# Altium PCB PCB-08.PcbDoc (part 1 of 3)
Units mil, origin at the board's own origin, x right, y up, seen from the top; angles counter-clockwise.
Board outline 2372.23 x 1978.53 mil, 4 copper layers (Top Layer, Plane-1, Plane-2, Bottom Layer), stack 84.834 mil thick; 206 components, 83 nets, 492 pads, 242 vias.
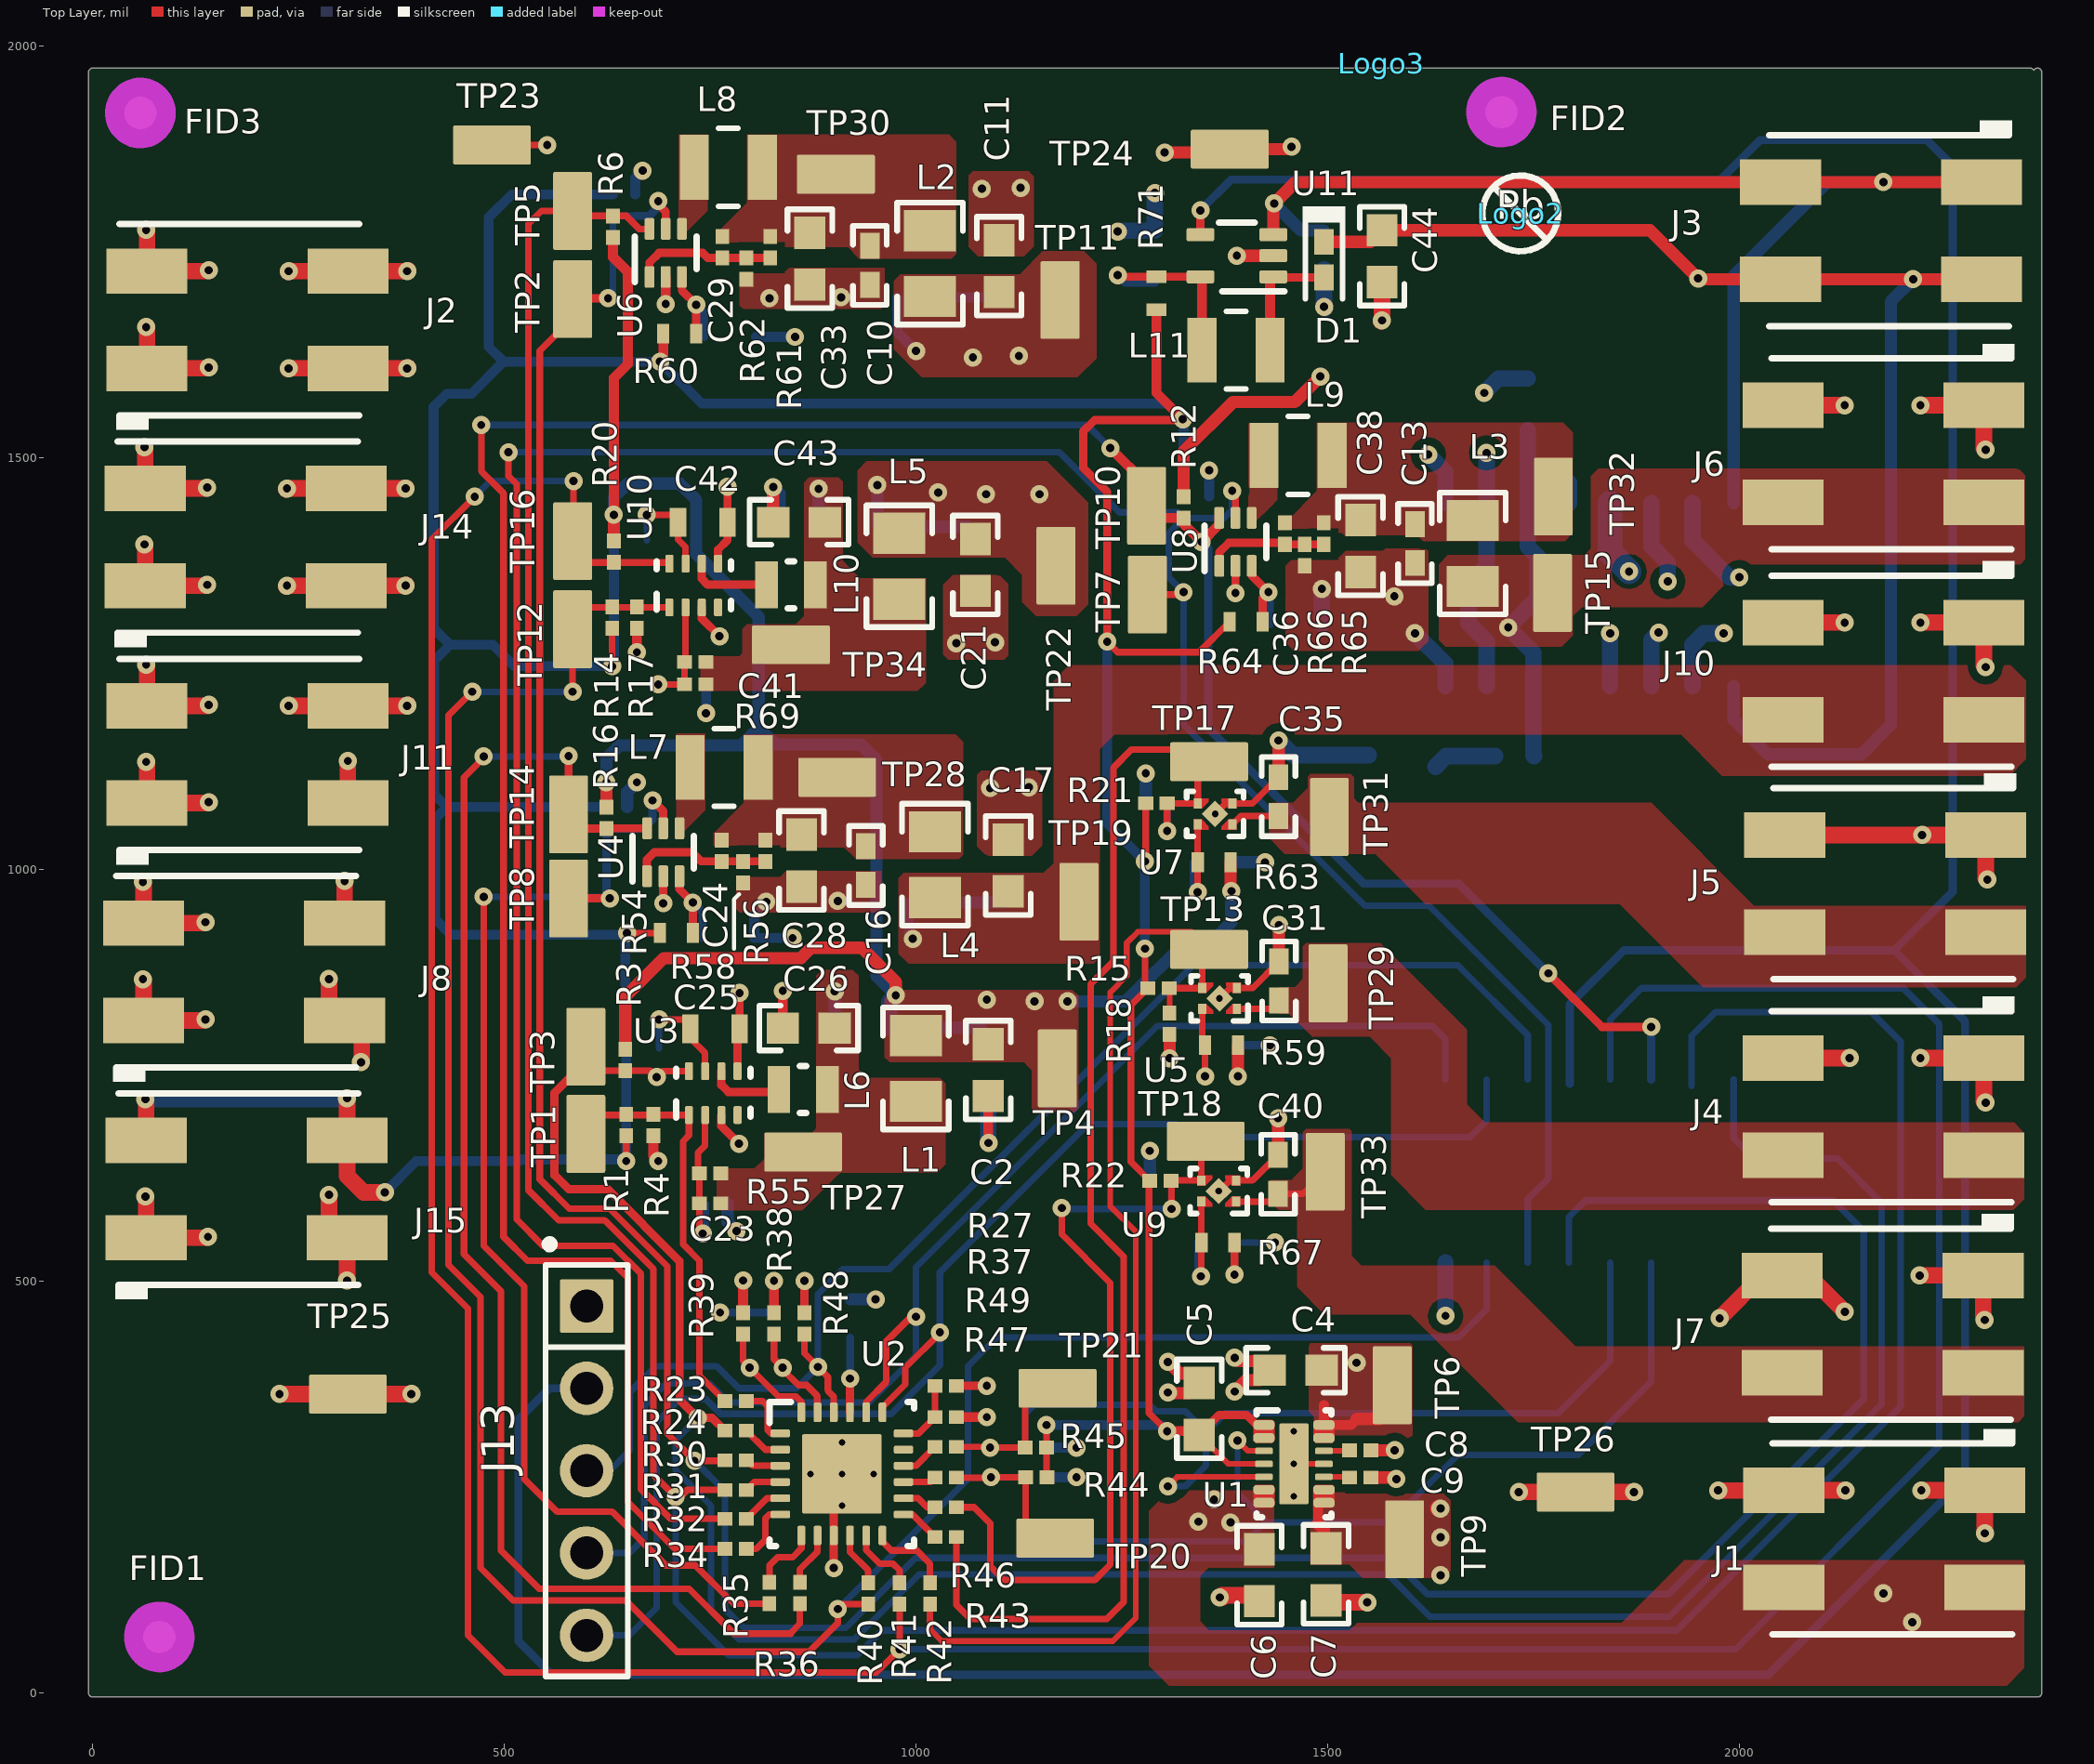
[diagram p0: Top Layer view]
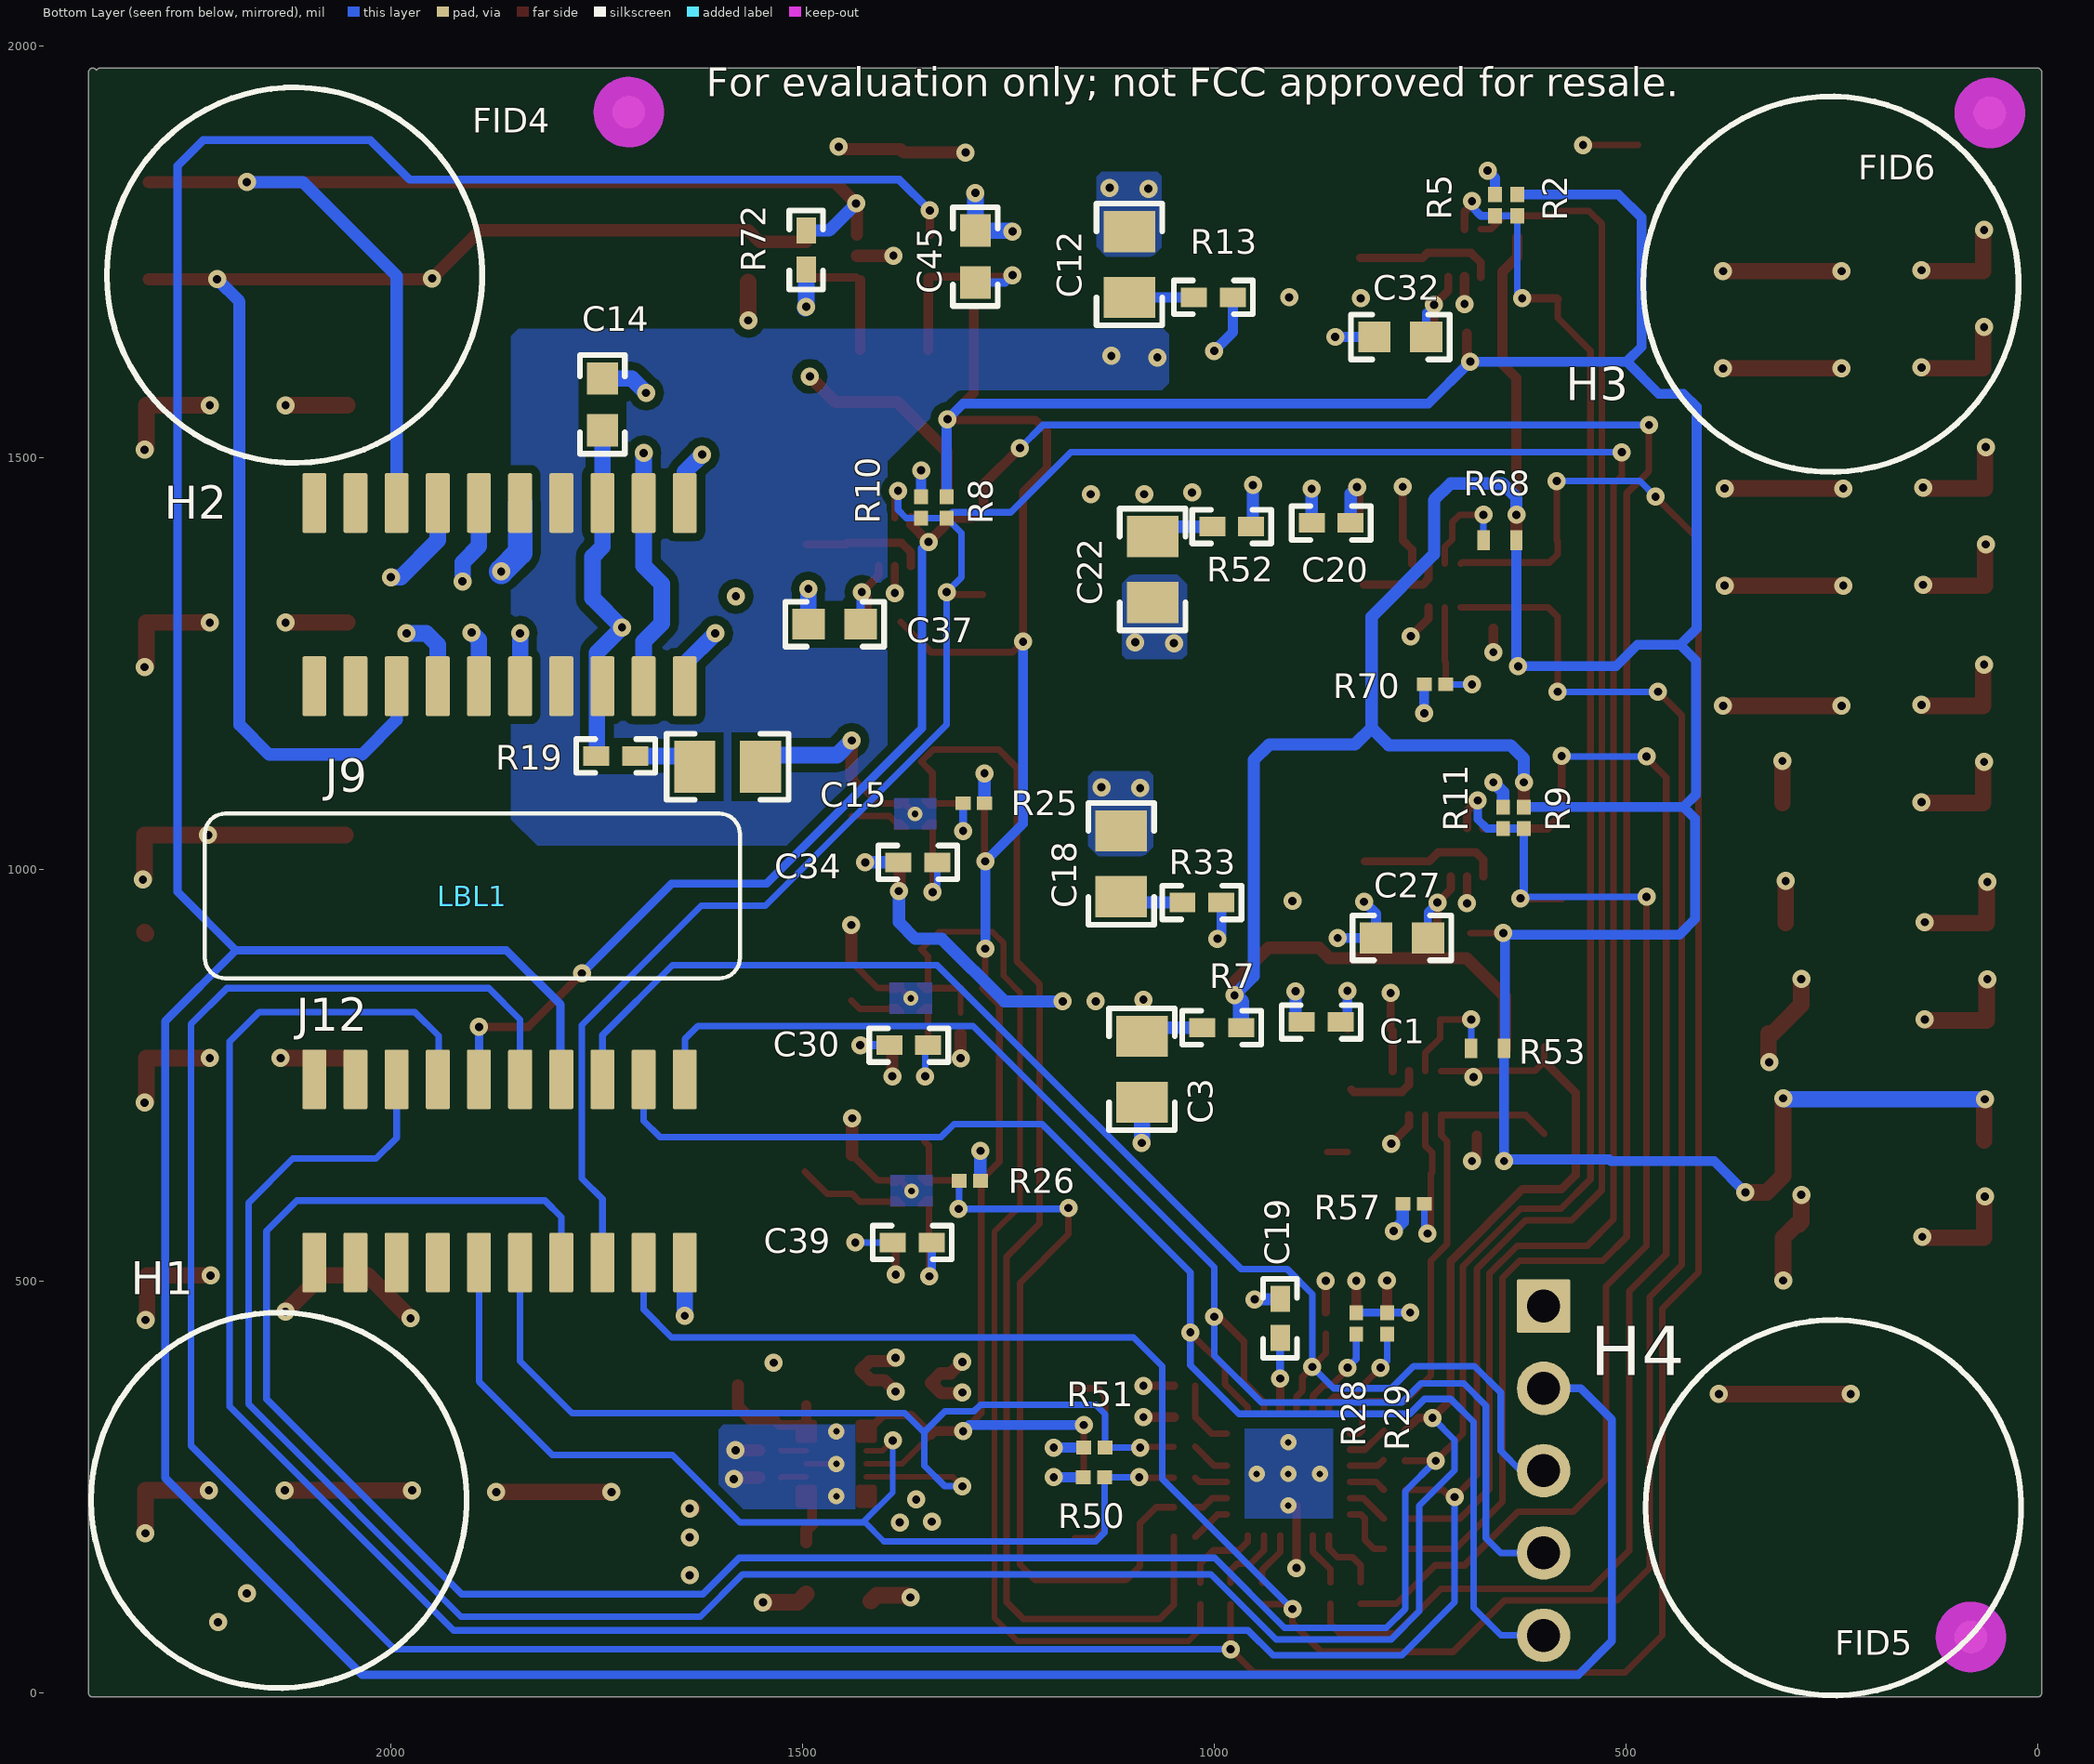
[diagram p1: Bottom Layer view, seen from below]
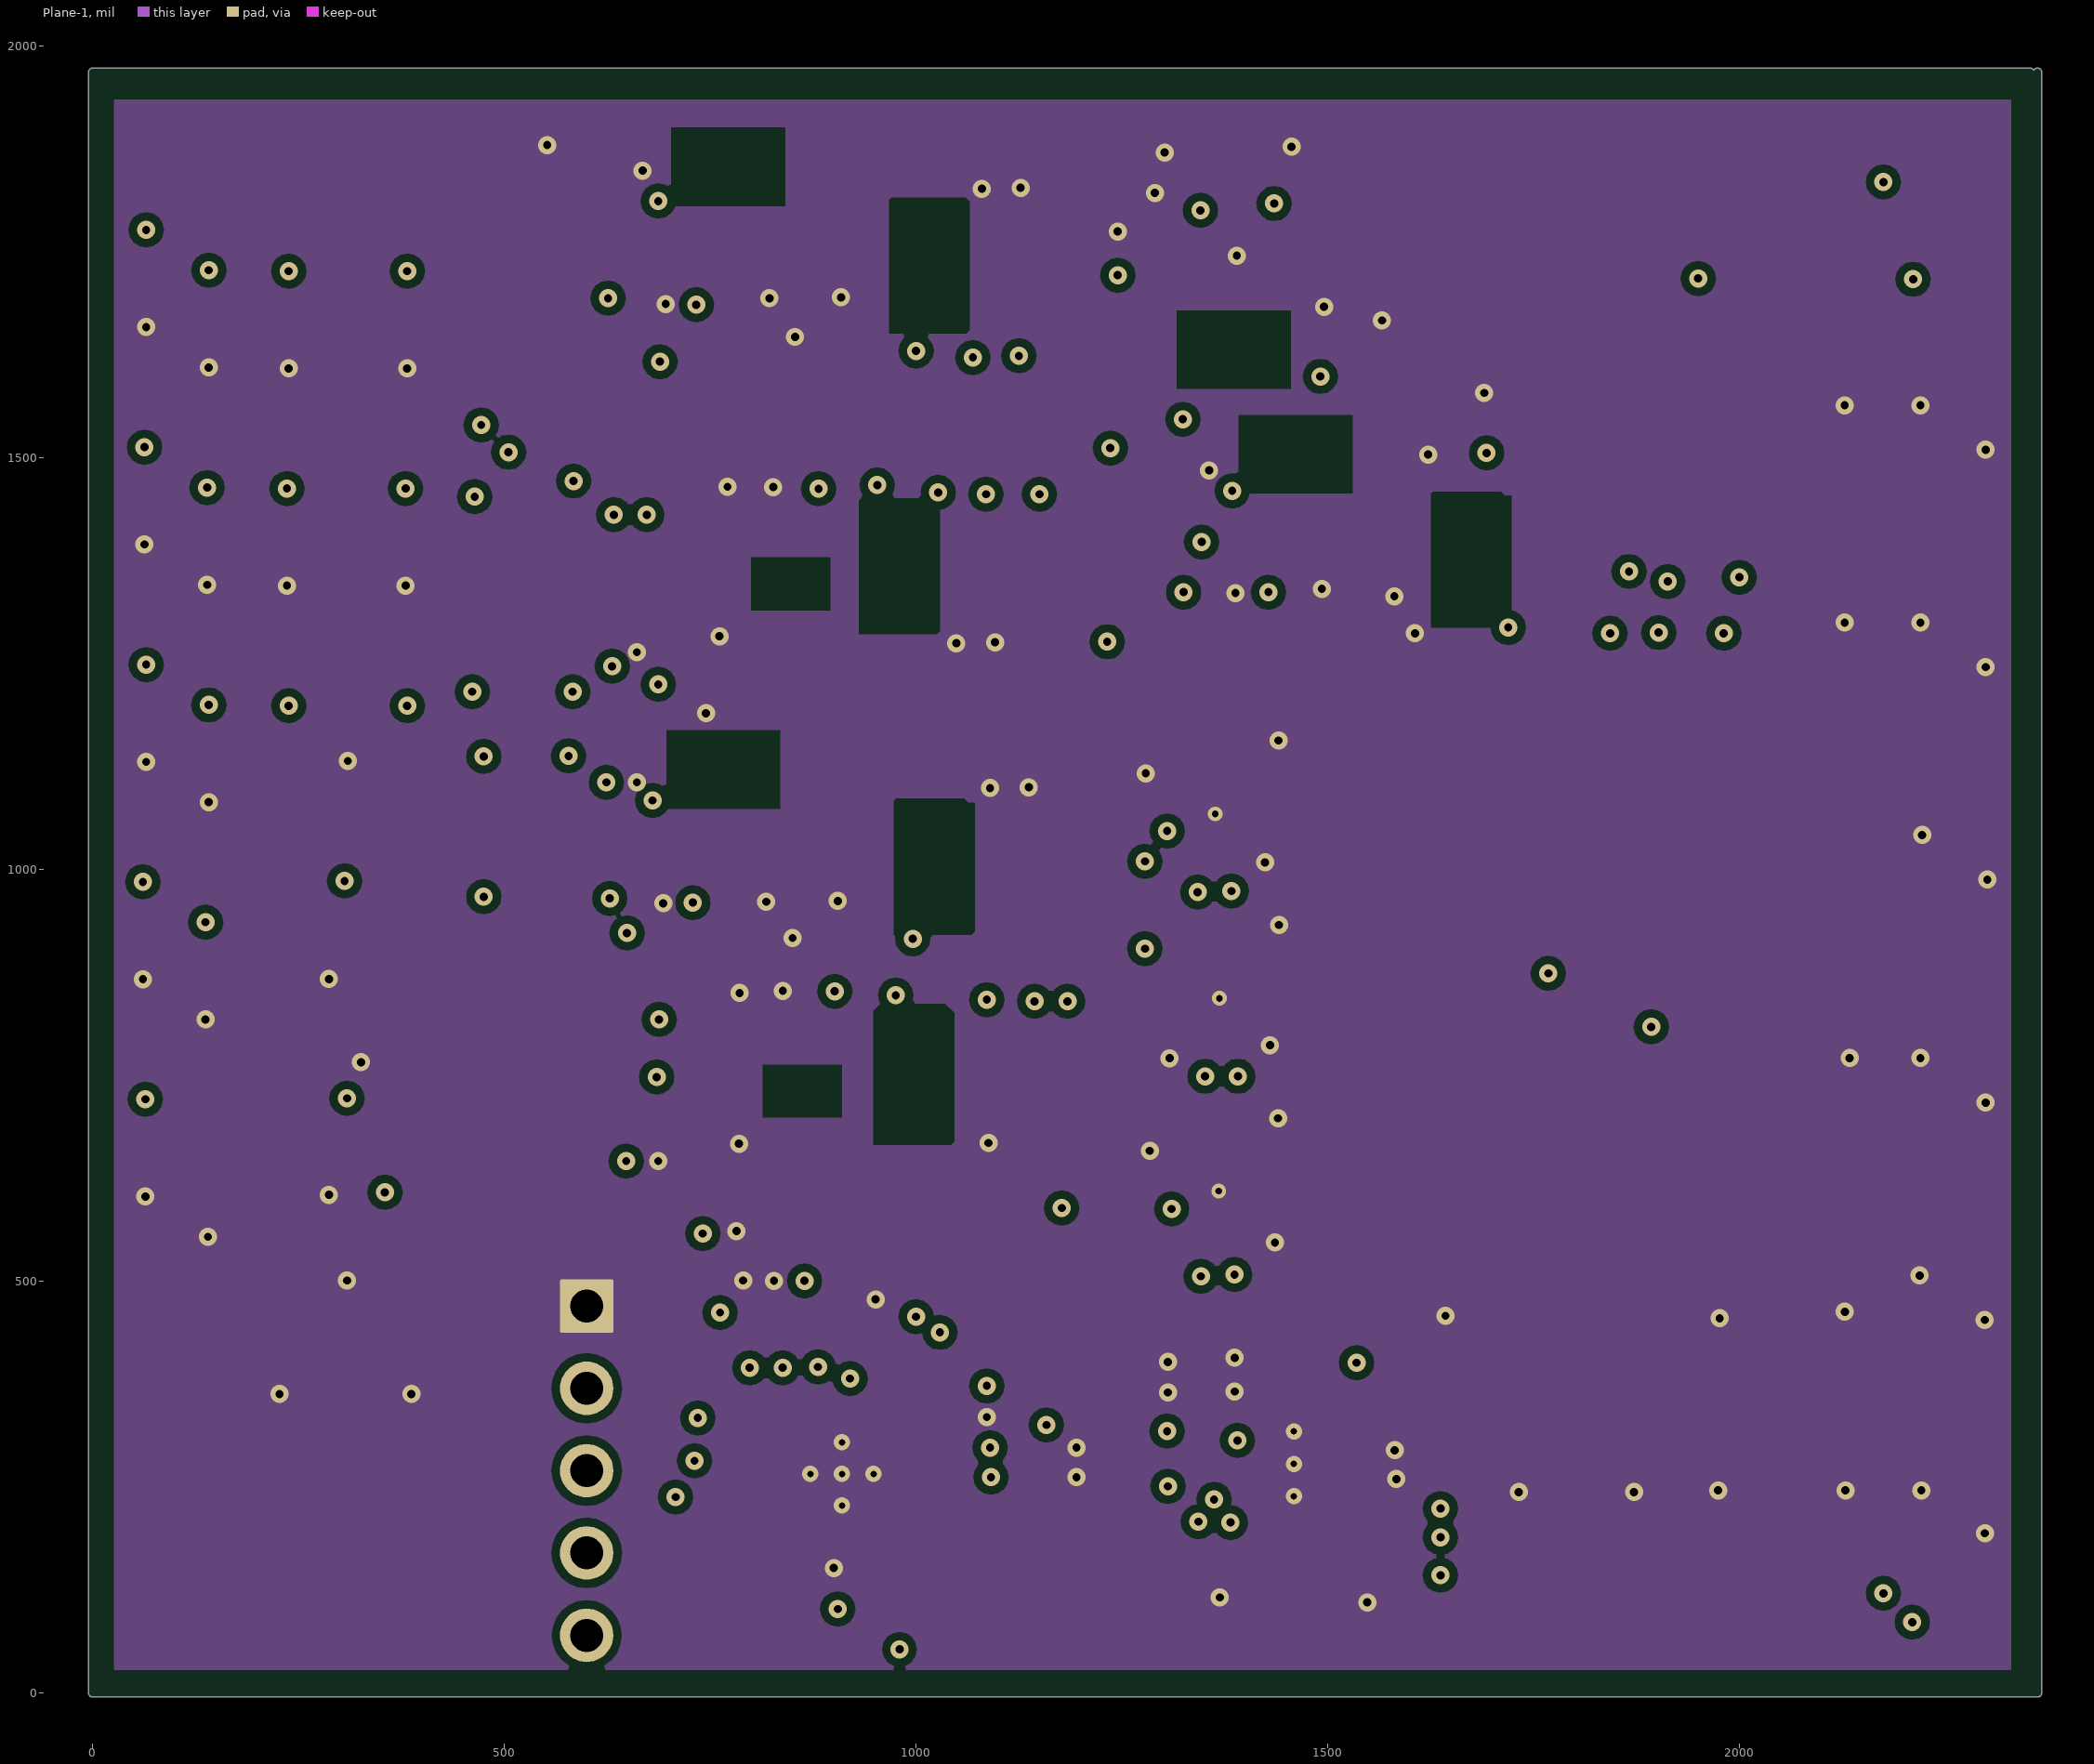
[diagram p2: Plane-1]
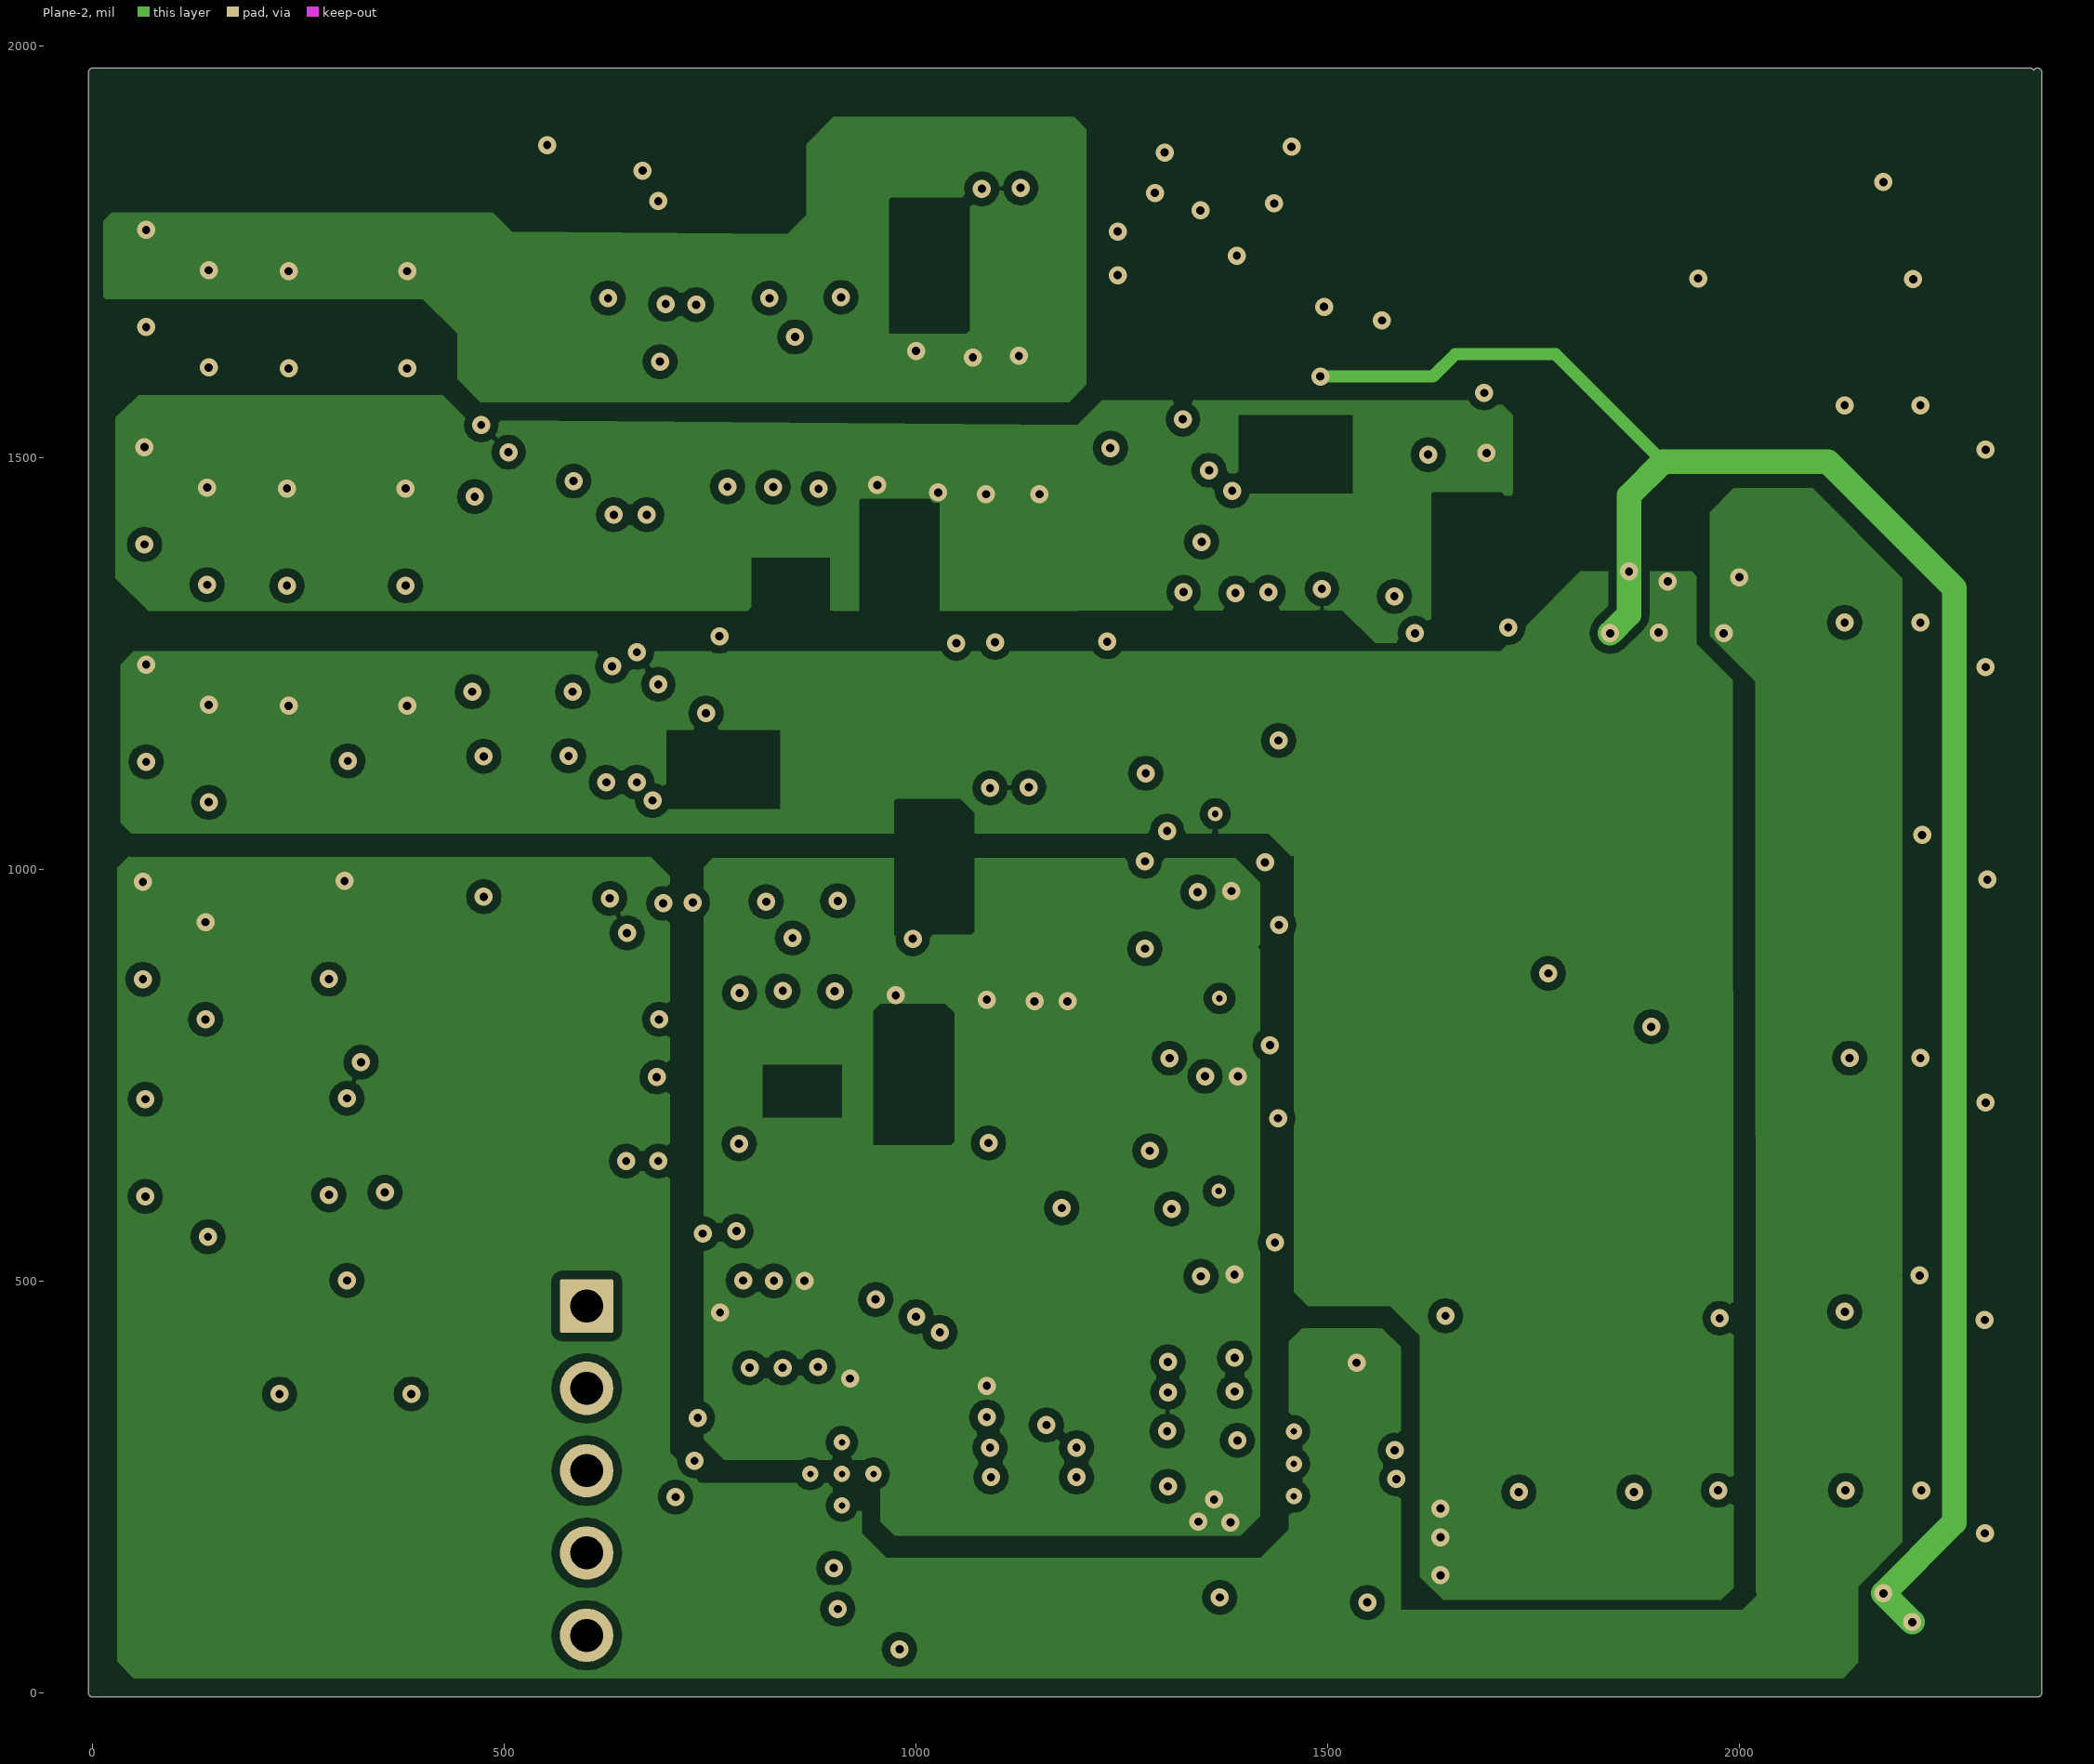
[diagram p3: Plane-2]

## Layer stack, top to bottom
Top Solder: solder mask 0.4, Solder Resist, Dk 3.5
Top Layer: signal copper 1.4
Dielectric1: core 59.2, FR-4, Dk 4.8
Plane-1: signal copper 1.417
Dielectric 2: dielectric 10, Dk 4.2
Plane-2: signal copper 1.417
Dielectric 3: dielectric 10, Dk 4.2
Bottom Layer: signal copper 1.4
Bottom Solder: solder mask 0.4, Solder Resist, Dk 3.5

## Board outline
0,-5.01 cw(c0,0) -5.01,0 -5.01,1968.5 cw(c0,1968.5) 0,1973.52 2353.2,1973.52 cw(c2353.2,1968.5) 2357.7,1970.72 cw(c2362.2,1968.5) 2367.22,1968.5 2367.22,0 cw(c2362.2,0) 2362.2,-5.01

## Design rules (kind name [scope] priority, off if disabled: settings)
AcuteAngle [All] p1 off: minimum=4.50000000000000E+0001 checktracksonly=FALSE
AssemblyTestPointUsage [All] p1 off: valid=2
AssemblyTestpoint [All] p1 off: testpointundercomponent=TRUE minsize=40 maxsize=100 preferedsize=60 minholesize=0 maxholesize=40 preferedholesize=32 testpointgrid=1 usegrid=TRUE gridtolerance=0.01 allowsidetop=TRUE allowsidebottom=TRUE
Clearance Clearance_U5_pads [InPadClass('U5-pad')] p1: gap=4.5 ignorepadtopadclearanceinfootprint=FALSE except(0: Arc-Hole Track-Hole SMDPad-Hole THPad-Hole Via-Hole Fill-Hole Poly-Hole Region-Hole Text-Hole)
Clearance Clearance_u1_pads [InPadClass('U1-pad')] p2: gap=5 ignorepadtopadclearanceinfootprint=FALSE except(0: Arc-Hole Track-Hole SMDPad-Hole THPad-Hole Via-Hole Fill-Hole Poly-Hole Region-Hole Text-Hole)
Clearance Clearance_samenets [IsPad vs IsVia] p3: gap=6 ignorepadtopadclearanceinfootprint=FALSE except(0: Arc-Track Arc-Hole Track-Track Track-Hole SMDPad-Hole THPad-Hole Via-Hole Fill-Hole Poly-Hole Region-Hole Text-Hole)
Clearance Clearance_Keepouts [((IsTrack Or IsArc) And Not InPoly) And IsFree and IsKeepOut vs ((IsTrack Or IsArc) And Not InPoly) And IsFree and IsKeepOut] p4: gap=0 ignorepadtopadclearanceinfootprint=FALSE
Clearance Clearance_Poly [InPolygon] p5: gap=10 ignorepadtopadclearanceinfootprint=FALSE except(0: Arc-Hole Track-Hole SMDPad-Hole THPad-Hole Via-Hole Fill-Hole Poly-Hole Region-Hole Text-Hole)
Clearance Clearance_FiducialMark [IsKeepOut and InComponentClass('FiducialMark') vs IsPad and InComponentClass('FiducialMark')] p6: gap=0 ignorepadtopadclearanceinfootprint=FALSE
Clearance [All] p7: gap=6 ignorepadtopadclearanceinfootprint=FALSE except(0: Arc-Hole Track-Hole SMDPad-Hole THPad-Hole Via-Hole Fill-Hole Poly-Hole Region-Hole Text-Hole)
ComponentClearance ComponentClearance_MountingHoles_FiducialMarks [InComponentClass('Mounting Holes') vs InComponentClass('FiducialMark')] p1: gap=50 collisioncheckmode=3 verticalgap=10 showdistances=FALSE
ComponentClearance ComponentClearance_Shunt [InComponentClass('Header') vs InComponentClass('Shunt')] p2: gap=0 collisioncheckmode=3 verticalgap=0 showdistances=FALSE
ComponentClearance ComponentClearance_Logo [InComponentClass('Logo')] p3: gap=50 collisioncheckmode=3 verticalgap=10 showdistances=FALSE
ComponentClearance ComponentClearance_ScrewToNut [(HasFootprint('NY PMS 440 0025 PH')) vs (HasFootprint('Keystone_1902C'))] p4: gap=5 collisioncheckmode=3 verticalgap=10 showdistances=FALSE
ComponentClearance ComponentClearance_MountingHoles [InComponentClass('Mounting Holes')] p5: gap=250 collisioncheckmode=3 verticalgap=100000 showdistances=FALSE
ComponentClearance ComponentClearance_SmallPassives [HasFootprint('0201*') or HasFootprint('0402*') or HasFootprint('0508') or HasFootprint('0603*') or HasFootprint('0612') or HasFootprint('0805*') or HasFootprint('0815*') or HasFootprint('0830*') or HasFootprint('1206*') or HasFootprint('1210*') or HasFootprint('1808*') or HasFootprint('1812*') or HasFootprint('1825*') or HasFootprint('2010*') or HasFootprint('2220*') or HasFootprint('2225*') or HasFootprint('2512*') or HasFootprint('2728*') or HasFootprint('3518*') vs HasFootprint('0201*') or HasFootprint('0402*') or HasFootprint('0508') or HasFootprint('0603*') or HasFootprint('0612') or HasFootprint('0805*') or HasFootprint('0815*') or HasFootprint('0830*') or HasFootprint('1206*') or HasFootprint('1210*') or HasFootprint('1808*') or HasFootprint('1812*') or HasFootprint('1825*') or HasFootprint('2010*') or HasFootprint('2220*') or HasFootprint('2225*') or HasFootprint('2512*') or HasFootprint('2728*') or HasFootprint('3518*')] p6: gap=10 collisioncheckmode=3 verticalgap=10 showdistances=FALSE
ComponentClearance ComponentClearance_THtoSMT [IsThruComponent vs IsSMTComponent] p7: gap=20 collisioncheckmode=3 verticalgap=30 showdistances=FALSE
ComponentClearance ComponentClearance_THtoTH [IsThruComponent vs IsThruComponent] p8: gap=30 collisioncheckmode=3 verticalgap=30 showdistances=FALSE
ComponentClearance [All] p9: gap=20 collisioncheckmode=3 verticalgap=10 showdistances=FALSE
DiffPairsRouting [All] p1 off: maxlimit=100 minlimit=10 mostfreqgap=10 toplayer_minwidth=15 toplayer_maxwidth=15 toplayer_prefwidth=15 midlayer1_minwidth=15 midlayer1_maxwidth=15 midlayer1_prefwidth=15 midlayer2_minwidth=15 midlayer2_maxwidth=15 midlayer2_prefwidth=15 bottomlayer_minwidth=15 bottomlayer_maxwidth=15 bottomlayer_prefwidth=15 maxuncoupledlength=1000
FabricationTestPointUsage TestPointUsage [All] p1 off: valid=2 allowmultiple=FALSE
FabricationTestpoint Testpoint [All] p1 off: side=3 testpointundercomponent=TRUE minsize=40 maxsize=100 preferedsize=60 minholesize=0 maxholesize=40 preferedholesize=32 testpointgrid=1 allowsidetop=TRUE allowsidebottom=TRUE usegrid=TRUE gridtolerance=0.01
FanoutControl Fanout_LCC [IsLCC] p1 off: bgadir=Out bgaviamode=Centered fanoutstyle=Auto fanoutdirection=Alternating viagrid=1 // Fanout_LCC (Default Rule)
FanoutControl Fanout_BGA [IsBGA] p2 off: bgadir=Out bgaviamode=Centered fanoutstyle=Auto fanoutdirection=Alternating viagrid=1 // Fanout_BGA (Default Rule)
FanoutControl Fanout_SOIC [IsSOIC] p3 off: bgadir=Out bgaviamode=Centered fanoutstyle=Auto fanoutdirection=Alternating viagrid=1 // Fanout_SOIC (Default Rule)
FanoutControl Fanout_Default [All] p4 off: bgadir=Out bgaviamode=Centered fanoutstyle=Auto fanoutdirection=Alternating viagrid=1 // Fanout_Default (Default Rule)
FanoutControl Fanout_Small [(CompPinCount < 5)] p5 off: bgadir=Out bgaviamode=Centered fanoutstyle=Auto fanoutdirection=OutThenIn viagrid=1 // Fanout_Small (Default Rule)
HoleSize [All] p1 off: absolutevalues=TRUE maxlimit=251 minlimit=7.87 maxpercent=80.000 minpercent=20.000
HoleToHoleClearance [All] p1 off: gap=10 allowstackedmicrovias=TRUE
LayerPairs [All] p1 off: enforce=TRUE
MinimumAnnularRing MinimumAnnularRing_ThermalPadVias [IsVia and InAnyComponent] p1 off: minimumring=5.91
MinimumAnnularRing [All] p2 off: minimumring=8
MinimumSolderMaskSliver MinimumSolderMaskSliver_Logo [InComponentClass('Logo') vs InComponentClass('Logo')] p1 off: minsoldermaskwidth=0.7
MinimumSolderMaskSliver [All] p2 off: minsoldermaskwidth=3.94
NetAntennae [All] p1 off: netantennaetolerance=0
PlaneConnect [All] p1: planeconnectstyle=Relief reliefexpansion=10 reliefentries=4 reliefconductorwidth=10 reliefairgap=10
PolygonConnect [All] p1: connectstyle=Direct reliefconductorwidth=10 reliefentries=4 polygonreliefangle="90 Angle" airgapwidth=10
RoutingCorners [All] p1 off: cornerstyle=45-Degree minsetback=100 maxsetback=100
RoutingLayers [All] p1 off: top layer_v5=TRUE mid layer 1_v5=TRUE mid layer 2_v5=TRUE bottom layer_v5=TRUE
RoutingPriority [All] p1 off: routingpriority=0
RoutingTopology [All] p1 off: topology=Shortest
RoutingVias ThermalPadVias [IsVia and InAnyComponent] p1 off: holewidth=7.87 width=19.68 viastyle="Through Hole" minholewidth=7.87 minwidth=19.68 maxholewidth=12.99 maxwidth=23.62
RoutingVias [All] p2: holewidth=10 width=22 viastyle="Through Hole" minholewidth=7.87 minwidth=20 maxholewidth=40 maxwidth=65
SilkToBoardRegionClearance [Not ((IsComment or IsDesignator) And (Hide <> 'False')) and not InRegion(1000,500,4000,800)] p1:
SilkToSilkClearance SilkToSilkClearance_Pb-FreeLogo [(HasFootprint('Pb-Free_Overlay_Medium') OR HasFootprint('Pb-Free_Overlay_Small')) vs (HasFootprint('Pb-Free_Overlay_Medium') OR HasFootprint('Pb-Free_Overlay_Small'))] p1 off: silktosilkclearance=0
SilkToSilkClearance [All] p2 off: silktosilkclearance=4
SilkToSolderMaskClearance SilkToComponentPadClearance [(IsPad or IsFill or IsRegion) and InAnycomponent] p1 off: minsilkscreentomaskgap=5 clearancetoexposedcopper=TRUE
SilkToSolderMaskClearance "Silk to Solder Mask Opening" [All] p2 off: minsilkscreentomaskgap=4 clearancetoexposedcopper=FALSE
SolderMaskExpansion [All] p1 off: expansion=1.97
ViasUnderSMD [All] p1: allowed=TRUE
Width [All] p1: maxlimit=100 minlimit=6 preferedwidth=10 checkconnectedcopper=TRUE
6 further rules are at their usual default settings.

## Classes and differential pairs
pad class U5-pad: U5-1 U5-2 U5-3 U5-4 U5-5 U7-1 U7-2 U7-3 U7-4 U7-5 U9-1 U9-2 U9-3 U9-4 U9-5
pad class U1-pad: U1-1 U1-2 U1-3 U1-4 U1-5 U1-6 U1-7 U1-8 U1-9 U1-10 U1-11 U1-12 U1-13 U1-14 U1-15
net class U11_Nets: GND LED_PWM NetC45_1 NetD1_2 nLED
net class U10_Nets: EN_1V1 GND NetC41_2 NetC42_1 NetL10_1 PG_1V1
net class U9_Nets: EN_L1V8B GND L1V8B NetC39_1
net class U8_Nets: EN_1V35 GND NetC36_2 NetC37_1 NetL9_1 PG_1V35
net class U7_Nets: EN_L1V8A GND L1V8A NetC34_1
net class U6_Nets: EN_1V8 GND NetC29_2 NetC32_1 NetL8_1 PG_1V8
net class U5_Nets: EN_L2V8 GND L2V8 NetC30_1
net class U4_Nets: EN_1V2 GND NetC24_2 NetC27_1 NetL7_1 PG_1V2
net class U3_Nets: EN_3V3 GND NetC23_2 NetC25_1 NetL6_1 PG_3V3
net class U2_Nets: 3V3 GND I2C_INT NetR23_2 NetR24_2 NetR27_1 NetR28_1 NetR29_1 NetR30_2 NetR31_2 NetR32_2 NetR34_2 NetR35_2 NetR36_2 NetR40_2 NetR41_2 NetR42_2 NetR43_2 NetR46_2 NetR47_2 NetR49_2 SCL SDA
net class U1_Nets: 3V3 EN_G3V3 EN_G5V G3V3 G5V GND NetC8_1 NetC9_1 PLLUP
net class TP34_Nets: V1V1
net class TP33_Nets: L1V8B
net class TP32_Nets: V1V35
net class TP31_Nets: L1V8A
net class TP30_Nets: V1V8
net class TP29_Nets: L2V8
net class TP28_Nets: V1V2
net class TP27_Nets: V3V3
net class TP26_Nets: GND
net class TP25_Nets: GND
net class TP24_Nets: GND
net class TP23_Nets: GND
net class TP22_Nets: 1V1
net class TP21_Nets: EN_G3V3
net class TP20_Nets: EN_G5V
net class TP19_Nets: 1V2
net class TP18_Nets: EN_L1V8B
net class TP17_Nets: EN_L1V8A
net class TP16_Nets: PG_1V1
net class TP15_Nets: 1V35
net class TP14_Nets: PG_1V2
net class TP13_Nets: EN_L2V8
net class TP12_Nets: EN_1V1
net class TP11_Nets: 1V8
net class TP10_Nets: PG_1V35
net class TP9_Nets: G3V3
net class TP8_Nets: EN_1V2
net class TP7_Nets: EN_1V35
net class TP6_Nets: G5V
net class TP5_Nets: PG_1V8
net class TP4_Nets: 3V3
net class TP3_Nets: PG_3V3
net class TP2_Nets: EN_1V8
net class TP1_Nets: EN_3V3
net class R72_Nets: GND nLED
net class R71_Nets: NetC45_1 PLLUP
net class R70_Nets: GND NetC41_2
net class R69_Nets: NetC41_2 V1V1
net class R68_Nets: NetC42_1 PLLUP
net class R67_Nets: 3V3 NetC39_1
net class R66_Nets: GND NetC36_2
net class R65_Nets: NetC36_2 V1V35
net class R64_Nets: NetC37_1 PLLUP
net class R63_Nets: 3V3 NetC34_1
net class R62_Nets: GND NetC29_2
net class R61_Nets: NetC29_2 V1V8
net class R60_Nets: NetC32_1 PLLUP
net class R59_Nets: 3V3 NetC30_1
net class R58_Nets: GND NetC24_2
net class R57_Nets: GND NetC23_2
net class R56_Nets: NetC24_2 V1V2
net class R55_Nets: NetC23_2 V3V3
net class R54_Nets: NetC27_1 PLLUP
net class R53_Nets: NetC25_1 PLLUP
net class R52_Nets: 1V1 NetC22_1
net class R51_Nets: EN_G3V3 GND
net class R50_Nets: EN_G5V GND
net class R49_Nets: EN_G3V3 NetR49_2
net class R48_Nets: 3V3 I2C_INT
net class R47_Nets: EN_G5V NetR47_2
net class R46_Nets: EN_L1V8B NetR46_2
net class R45_Nets: EN_G3V3 PLLUP
net class R44_Nets: EN_G5V PLLUP
net class R43_Nets: EN_L1V8A NetR43_2
net class R42_Nets: EN_L2V8 NetR42_2
net class R41_Nets: NetR41_2 PG_1V1
net class R40_Nets: EN_1V1 NetR40_2
net class R39_Nets: GND NetR29_1
net class R38_Nets: GND NetR28_1
net class R37_Nets: GND NetR27_1
net class R36_Nets: NetR36_2 PG_1V2
net class R35_Nets: EN_1V2 NetR35_2
net class R34_Nets: NetR34_2 PG_1V35
net class R33_Nets: 1V2 NetC18_1
net class R32_Nets: EN_1V35 NetR32_2
net class R31_Nets: NetR31_2 PG_1V8
net class R30_Nets: EN_1V8 NetR30_2
net class R29_Nets: 3V3 NetR29_1
net class R28_Nets: 3V3 NetR28_1
net class R27_Nets: 3V3 NetR27_1
net class R26_Nets: EN_L1V8B GND
net class R25_Nets: EN_L1V8A GND
net class R24_Nets: NetR24_2 PG_3V3
net class R23_Nets: EN_3V3 NetR23_2
net class R22_Nets: EN_L1V8B PLLUP
net class R21_Nets: EN_L1V8A PLLUP
net class R20_Nets: 3V3 PG_1V1
net class R19_Nets: 1V35 NetC15_1
net class R18_Nets: EN_L2V8 GND
net class R17_Nets: EN_1V1 GND
net class R16_Nets: 3V3 PG_1V2
net class R15_Nets: EN_L2V8 PLLUP
net class R14_Nets: EN_1V1 PLLUP
net class R13_Nets: 1V8 NetC12_1
net class R12_Nets: 3V3 PG_1V35
net class R11_Nets: EN_1V2 GND
net class R10_Nets: EN_1V35 GND
net class R9_Nets: EN_1V2 PLLUP
net class R8_Nets: EN_1V35 PLLUP
net class R7_Nets: 3V3 NetC3_1
net class R6_Nets: 3V3 PG_1V8
net class R5_Nets: EN_1V8 GND
net class R4_Nets: EN_3V3 GND
net class R3_Nets: 3V3 PG_3V3
net class R2_Nets: EN_1V8 PLLUP
net class R1_Nets: EN_3V3 PLLUP
net class L11_Nets: NetC45_1 NetD1_2
net class L10_Nets: NetL10_1 V1V1
net class L9_Nets: NetL9_1 V1V35
net class L8_Nets: NetL8_1 V1V8
net class L7_Nets: NetL7_1 V1V2
net class L6_Nets: NetL6_1 V3V3
net class L5_Nets: 1V1 V1V1
net class L4_Nets: 1V2 V1V2
net class L3_Nets: 1V35 V1V35
net class L2_Nets: 1V8 V1V8
net class L1_Nets: 3V3 V3V3
net class J15_Nets: GND PLLUP
net class J14_Nets: 1V1 GND
net class J13_Nets: GND I2C_INT LED_PWM SCL SDA
net class J12_Nets: EN_1V1 EN_1V8 EN_1V35 EN_G3V3 EN_G5V GND I2C_INT LED_PWM PG_1V1 PG_1V8 PG_1V35 PG_3V3 SCL SDA
net class J11_Nets: G3V3 GND
net class J10_Nets: 1V2 GND
net class J9_Nets: 1V1 1V8 1V35 3V3 G3V3 G5V GND nLED pLED
net class J8_Nets: G5V GND
net class J7_Nets: GND L1V8B
net class J6_Nets: 1V35 GND
net class J5_Nets: GND L1V8A
net class J4_Nets: GND L2V8
net class J3_Nets: nLED pLED
net class J2_Nets: 1V8 GND
net class J1_Nets: 3V3 GND
net class D1_Nets: NetD1_2 pLED
net class C45_Nets: GND NetC45_1
net class C44_Nets: GND pLED
net class C43_Nets: GND V1V1
net class C42_Nets: GND NetC42_1
net class C41_Nets: NetC41_2 V1V1
net class C40_Nets: GND L1V8B
net class C39_Nets: GND NetC39_1
net class C38_Nets: GND V1V35
net class C37_Nets: GND NetC37_1
net class C36_Nets: NetC36_2 V1V35
net class C35_Nets: GND L1V8A
net class C34_Nets: GND NetC34_1
net class C33_Nets: GND V1V8
net class C32_Nets: GND NetC32_1
net class C31_Nets: GND L2V8
net class C30_Nets: GND NetC30_1
net class C29_Nets: NetC29_2 V1V8
net class C28_Nets: GND V1V2
net class C27_Nets: GND NetC27_1
net class C26_Nets: GND V3V3
net class C25_Nets: GND NetC25_1
net class C24_Nets: NetC24_2 V1V2
net class C23_Nets: NetC23_2 V3V3
net class C22_Nets: GND NetC22_1
net class C21_Nets: 1V1 GND
net class C20_Nets: GND V1V1
net class C19_Nets: 3V3 GND
net class C18_Nets: GND NetC18_1
net class C17_Nets: 1V2 GND
net class C16_Nets: GND V1V2
net class C15_Nets: GND NetC15_1
net class C14_Nets: 1V35 GND
net class C13_Nets: GND V1V35
net class C12_Nets: GND NetC12_1
net class C11_Nets: 1V8 GND
net class C10_Nets: GND V1V8
net class C9_Nets: GND NetC9_1
net class C8_Nets: GND NetC8_1
net class C7_Nets: G3V3 GND
net class C6_Nets: 3V3 GND
net class C5_Nets: GND PLLUP
net class C4_Nets: G5V GND
net class C3_Nets: GND NetC3_1
net class C2_Nets: 3V3 GND
net class C1_Nets: GND V3V3
component class "TIDA-01579 Point of Load": C23 C24 C25 C26 C27 C28 C29 C30 C31 C32 C33 C34 C35 C36 C37 C38 C39 C40 C41 C42 C43 C44 C45 D1 J15 L6 L7 L8 L9 L10 L11 R53 R54 R55 R56 R57 R58 R59 R60 R61 R62 R63 R64 R65 R66 R67 R68 R69 R70 R71 R72 TP27 TP28 TP29 TP30 TP31 TP32 TP33 TP34 U3 U4 U5 U6 U7 U8 U9 U10 U11
component class "TIDA-01579 Other": C1 C2 C3 C4 C5 C6 C7 C8 C9 C10 C11 C12 C13 C14 C15 C16 C17 C18 C19 C20 C21 C22 J1 J2 J3 J4 J5 J6 J7 J8 J9 J10 J11 J12 J13 J14 L1 L2 L3 L4 L5 R1 R2 R3 R4 R5 R6 R7 R8 R9 R10 R11 R12 R13 R14 R15 R16 R17 R18 R19 R20 R21 R22 R23 R24 R25 R26 R27 R28 R29 R30 R31 R32 R33 R34 R35 R36 R37 R38 R39 R40 R41 R42 R43 R44 R45 R46 R47 R48 R49 R50 R51 R52 TP1 TP2 TP3 TP4 TP5 TP6 TP7 TP8 TP9 TP10 TP11 TP12 TP13 TP14 TP15 TP16 TP17 TP18 TP19 TP20 TP21 TP22 TP23 TP24 TP25 TP26 U1 U2
component class Header: J13
component class AssemblyNote: ZZ1 ZZ2 ZZ3 ZZ4
component class FiducialMark: FID1 FID2 FID3 FID4 FID5 FID6
component class Label: LBL1
component class EVM_Hardware: FID1 FID2 FID3 FID4 FID5 FID6 H1 H2 H3 H4 LBL1 Logo2 Logo3 ZZ1 ZZ2 ZZ3 ZZ4

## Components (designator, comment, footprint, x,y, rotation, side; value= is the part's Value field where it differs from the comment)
C1 "0402ZC103KAT2A" 0402 870,815 r180 bottom value=0.01uF
C2 "GRM188R61A106ME69D" 0603 1087.76,756.5 r270 top value=10uF
C3 "GRM21BR61A476ME15L" 0805_HV 1087.76,757.5 r270 bottom value=47uF
C4 "GRM188R71C105KA12D" 0603 1461,392 r180 top value=1uF
C5 "GRM188Z71C475KE21D" 0603 1344,345 r90 top value=4.7uF
C6 "GRM188Z71C475KE21D" 0603 1417,143 r270 top value=4.7uF
C7 "GRM188R71A105KA61D" 0603 1498,144 r270 top value=1uF
C8 "C0603X5R1E102K030BA" 0201_033 1539.42,294.72 r0 top value=1000pF
C9 "C0603X5R1E102K030BA" 0201_033 1539.42,261.72 r0 top value=1000pF
C10 "0402ZC103KAT2A" 0402 944,1734 r270 top value=0.01uF
C11 "GRM188R61A106ME69D" 0603 1101,1733 r90 top value=10uF
C12 "GRM21BR61A476ME15L" 0805_HV 1103,1735 r90 bottom value=47uF
C13 "0402ZC103KAT2A" 0402 1606,1396 r270 top value=0.01uF
C14 "GRM188R61A106ME69D" 0603 1743,1565 r90 bottom value=10uF
C15 "GRM21BR61A476ME15L" 0805_HV 1591,1125 r180 bottom value=47uF
C16 "0402ZC103KAT2A" 0402 939,1005 r270 top value=0.01uF
C17 "GRM188R61A106ME69D" 0603 1112,1005 r90 top value=10uF
C18 "GRM21BR61A476ME15L" 0805_HV 1113,1007 r90 bottom value=47uF
C19 "GRM155R61A105ME15D" 0402 920,455 r90 bottom value=1uF
C20 "0402ZC103KAT2A" 0402 858,1421 r180 bottom value=0.01uF
C21 "GRM188R61A106ME69D" 0603 1072,1370 r270 top value=10uF
C22 "GRM21BR61A476ME15L" 0805_HV 1074.76,1364.5 r270 bottom value=47uF
C23 "GRM033R71E121KA01D" 0201 750,594.5 r180 top value=120pF
C24 "GRM0335C1H6R8BA01D" 0201 764,1023 r270 top value=6.8pF
C25 "GRM188Z71C475KE21D" 0603S 755.76,806.5 r0 top value=4.7uF
C26 "GRM188Z71A106MA73D" 0603 869.76,807.5 r180 top value=10uF
C27 "GRM188Z71C475KE21D" 0603 772,917 r0 bottom value=4.7uF
C28 "GRM188Z71A106MA73D" 0603 861,1011 r270 top value=10uF
C29 "GRM0335C1H6R8BA01D" 0201 765,1756 r270 top value=6.8pF
C30 "GRM155R61A105KE15D" 0402 1371,786.81 r0 bottom value=1uF
C31 "GRM155R61A105KE15D" 0402 1440.8,864.61 r90 top value=1uF
C32 "GRM188Z71C475KE21D" 0603 774,1647 r0 bottom value=4.7uF
C33 "GRM188Z71A106MA73D" 0603 871,1742 r270 top value=10uF
C34 "GRM155R61A105KE15D" 0402 1360,1008.81 r0 bottom value=1uF
C35 "GRM155R61A105KE15D" 0402 1440.33,1088.61 r90 top value=1uF
C36 "GRM0335C1H6R8BA01D" 0201 1448,1408 r270 top value=6.8pF
C37 "GRM188Z71C475KE21D" 0603 1461,1298 r0 bottom value=4.7uF
C38 "GRM188Z71A106MA73D" 0603 1540,1393 r270 top value=10uF
C39 "GRM155R61A105KE15D" 0402 1366.81,547 r0 bottom value=1uF
C40 "GRM155R61A105KE15D" 0402 1439.8,629.81 r90 top value=1uF
C41 "GRM033R71E121KA01D" 0201 732,1252 r180 top value=120pF
C42 "GRM188Z71C475KE21D" 0603S 741,1422 r0 top value=4.7uF
C43 "GRM188Z71A106MA73D" 0603 858,1422 r180 top value=10uF
C44 "C1608X7R1V105K080AC" 0603 1566,1745 r270 top value=1uF
C45 "GRM188Z71C475KE21D" 0603 1290.1,1744.61 r90 bottom value=4.7uF
D1 "NSR0240V2T1G" SOD-523 1495.52,1740.8 r270 top value=40V
FID1 "Fiducial" Fiducial10-20 81,68 r0 top
FID2 "Fiducial" Fiducial10-20 1711,1920 r0 top
FID3 "Fiducial" Fiducial10-20 58,1919 r0 top
FID4 "Fiducial" Fiducial10-20 1711,1920 r180 bottom
FID5 "Fiducial" Fiducial10-20 81,68 r180 bottom
FID6 "Fiducial" Fiducial10-20 58,1919 r180 bottom
H1 "SJ-5303 (CLEAR)" Bumpon_SJ5003Transparent 2136,234 r180 bottom
H2 "SJ-5303 (CLEAR)" Bumpon_SJ5003Transparent 2117,1722 r180 bottom
H3 "SJ-5303 (CLEAR)" Bumpon_SJ5003Transparent 251,1711 r180 bottom
H4 "SJ-5303 (CLEAR)" Bumpon_SJ5003Transparent 248,225 r90 bottom
J1 "2059-302/998-403" WAGO_2059-302 2176.05,187.06 r270 top
J2 "2059-302/998-403" WAGO_2059-302 188,1667.84 r90 top
J3 "2059-302/998-403" WAGO_2059-302 2172,1776 r270 top
J4 "2059-302/998-403" WAGO_2059-302 2175,712 r270 top
J5 "2059-302/998-403" WAGO_2059-302 2177.05,982.94 r270 top
J6 "2059-302/998-403" WAGO_2059-302 2175,1504.95 r270 top
J7 "2059-302/998-403" WAGO_2059-302 2174,448 r270 top
J8 "2059-302/998-403" WAGO_2059-302 184,875.89 r90 top
J9 "RSM-110-02-L-D" Samtec_RSM-110-02-x-D 1868,1334 r0 bottom
J10 "2059-302/998-403" WAGO_2059-302 2175,1241 r270 top
J11 "2059-302/998-403" WAGO_2059-302 188,1139.84 r90 top
J12 "RSM-110-02-L-D" Samtec_RSM-110-02-x-D 1868,634 r0 bottom
J13 "HTSW-105-07-G-S" Samtec_HTSW-105-07-G-S 600,270 r270 top
J14 "2059-302/998-403" WAGO_2059-302 186,1403.89 r90 top
J15 "2059-302/998-403" WAGO_2059-302 187.05,611.94 r90 top
L1 "74279220601" 0805_HV 999.76,758.5 r90 top value="600 ohm"
L2 "74279220601" 0805_HV 1017,1736 r270 top value="600 ohm"
L3 "74279220601" 0805_HV 1676,1384 r270 top value="600 ohm"
L4 "74279220601" 0805_HV 1023,1006 r270 top value="600 ohm"
L5 "74279220601" 0805_HV 979.76,1368.5 r90 top value="600 ohm"
L6 "74479275210" WE-PMCI_0805 863,733 r0 top value=1uH
L7 "DFE252012P-2R2M=P2" DFE252012P 767,1124 r0 top value=2.2uH
L8 "DFE252012P-2R2M=P2" DFE252012P 772,1853 r0 top value=2.2uH
L9 "DFE252012P-2R2M=P2" DFE252012P 1464,1503 r0 top value=2.2uH
L10 "74479275210" WE-PMCI_0805 848,1346 r0 top value=1uH
L11 "DFE252012PD-4R7M" DFE252012P 1388.66,1630.87 r0 top value=4.7uH
LBL1 "Size: 0.65\" x 0.20 \"" Label_650x200 1901,968 r0 bottom
Logo2 "Pb-Free Symbol" Pb-Free_Overlay_Small 1734,1797 r0 top
Logo3 "FCC disclaimer" FCC_disclaimer 1565,1979 r90 top
R1 "RC0201FR-07100KL" 0201 648,690 r90 top value=100k
R2 "RC0201FR-07100KL" 0201 632,1807 r270 bottom value=100k
R3 "RC0201FR-07100KL" 0201 647,769 r270 top value=100k
R4 "RC0201FR-07100KL" 0201 681,690 r270 top value=100k
R5 "RC0201FR-07100KL" 0201 659,1807 r90 bottom value=100k
R6 "RC0201FR-07100KL" 0201 632,1781 r90 top value=100k
R7 "ERJ-2BQFR33X" 0402 991,808 r180 bottom value=0.33
R8 "RC0201FR-07100KL" 0201 1325,1440 r270 bottom value=100k
R9 "RC0201FR-07100KL" 0201 624,1063 r270 bottom value=100k
R10 "RC0201FR-07100KL" 0201 1356,1440 r90 bottom value=100k
R11 "RC0201FR-07100KL" 0201 649,1063 r90 bottom value=100k
R12 "RC0201FR-07100KL" 0201 1325,1440 r270 top value=100k
R13 "ERJ-2BQFR33X" 0402 1001,1695 r180 bottom value=0.33
R14 "RC0201FR-07100KL" 0201 631,1306 r90 top value=100k
R15 "RC0201FR-07100KL" 0201 1294.5,856 r0 top value=100k
R16 "RC0201FR-07100KL" 0201 624,1063 r270 top value=100k
R17 "RC0201FR-07100KL" 0201 661,1306 r270 top value=100k
R18 "RC0201FR-07100KL" 0201 1308,813 r270 top value=100k
R19 "ERJ-2BQFR33X" 0402 1727,1138 r0 bottom value=0.33
R20 "RC0201FR-07100KL" 0201 633,1386 r270 top value=100k
R21 "RC0201FR-07100KL" 0201 1292,1080.5 r0 top value=100k
R22 "RC0201FR-07100KL" 0201 1296.99,622 r0 top value=100k
R23 "CRCW02010000Z0ED" 0201 780.98,354.5 r0 top value=0
R24 "CRCW02010000Z0ED" 0201 780.98,318.5 r0 top value=0
R25 "RC0201FR-07100KL" 0201 1292,1080.5 r180 bottom value=100k
R26 "RC0201FR-07100KL" 0201 1296.99,622 r180 bottom value=100k
R27 "RC0201FR-07100KL" 0201 1036,373 r0 top value=100k
R28 "RC0201FR-07100KL" 0201 827.5,449 r90 bottom value=100k
R29 "RC0201FR-07100KL" 0201 790.01,449 r90 bottom value=100k
R30 "CRCW02010000Z0ED" 0201 780.99,282.5 r0 top value=0
R31 "CRCW02010000Z0ED" 0201 780.99,246.5 r0 top value=0
R32 "CRCW02010000Z0ED" 0201 781,211.5 r0 top value=0
R33 "ERJ-2BQFR33X" 0402 1015,960 r180 bottom value=0.33
R34 "CRCW02010000Z0ED" 0201 781,175 r0 top value=0
R35 "CRCW02010000Z0ED" 0201 822,121.5 r90 top value=0
R36 "CRCW02010000Z0ED" 0201 859,121.5 r90 top value=0
R37 "CRCW02010000Z0ED" 0201 1036.01,335 r180 top value=0
R38 "CRCW02010000Z0ED" 0201 827.5,449 r270 top value=0
R39 "CRCW02010000Z0ED" 0201 790.01,449 r270 top value=0
R40 "CRCW02010000Z0ED" 0201 942,120.99 r90 top value=0
R41 "CRCW02010000Z0ED" 0201 980,120.99 r90 top value=0
R42 "CRCW02010000Z0ED" 0201 1017,120.99 r90 top value=0
R43 "CRCW02010000Z0ED" 0201 1036,189.5 r180 top value=0
R44 "RC0201FR-07100KL" 0201 1146,262 r180 top value=100k
R45 "RC0201FR-07100KL" 0201 1145.5,298 r180 top value=100k
R46 "CRCW02010000Z0ED" 0201 1036,225.5 r180 top value=0
R47 "CRCW02010000Z0ED" 0201 1036,261.5 r180 top value=0
R48 "RC0201FR-07100KL" 0201 864.5,449 r270 top value=100k
R49 "CRCW02010000Z0ED" 0201 1036.01,299 r180 top value=0
R50 "RC0201FR-07100KL" 0201 1146,262 r0 bottom value=100k
R51 "RC0201FR-07100KL" 0201 1145.5,298 r0 bottom value=100k
R52 "ERJ-2BQFR33X" 0402 978.76,1416.5 r180 bottom value=0.33
R53 "RC0402JR-070RL" 0402S 668,783 r0 bottom value=0
R54 "RC0402JR-070RL" 0402S 709,923 r0 top value=0
R55 "RC0201FR-07453KL" 0201 750,631 r180 top value=453k
R56 "RC0201FR-07100KL" 0201 817,1023 r270 top value=100k
R57 "RC0201FR-07100KL" 0201 758,594 r0 bottom value=100k
R58 "RC0201FR-07100KL" 0201 790,997 r270 top value=100k
R59 "RC0402JR-070RL" 0402S 1371,786.81 r180 top value=0
R60 "RC0402JR-070RL" 0402S 713,1651 r0 top value=0
R61 "RC0201FR-7D200KL" 0201 823,1756 r270 top value=200k
R62 "RC0201FR-07100KL" 0201 794,1730 r270 top value=100k
R63 "RC0402JR-070RL" 0402S 1362.12,1008.81 r180 top value=0
R64 "RC0402JR-070RL" 0402S 1401,1301 r0 top value=0
R65 "RC0201FR-07124KL" 0201 1495,1408 r270 top value=124k
R66 "RC0201FR-07100KL" 0201 1472,1382 r270 top value=100k
R67 "RC0402JR-070RL" 0402S 1366.81,547 r180 top value=0
R68 "RC0402JR-070RL" 0402S 653,1400 r0 bottom value=0
R69 "RC0201FR-0782K5L" 0201 732,1225 r180 top value=82.5k
R70 "RC0201FR-07100KL" 0201 732,1225 r0 bottom value=100k
R71 "RC0402JR-070RL" 0402S 1292,1700 r90 top value=0
R72 "RCS04022R20FKED" 0402 1495.52,1752.61 r270 bottom value=2.20
TP1 "RCU-0C" TE_RCU 599,679 r270 top
TP2 "RCU-0C" TE_RCU 583,1693 r270 top
TP3 "RCU-0C" TE_RCU 599,785 r270 top
TP4 "RCU-0C" TE_RCU 1171.69,758.5 r270 top
TP5 "RCU-0C" TE_RCU 583,1800 r270 top
TP6 "RCU-0C" TE_RCU 1578.42,373.72 r90 top
TP7 "RCU-0C" TE_RCU 1281,1334 r270 top
TP8 "RCU-0C" TE_RCU 578,965 r270 top
TP9 "RCU-0C" TE_RCU 1593.42,186.72 r90 top
TP10 "RCU-0C" TE_RCU 1280,1442 r270 top
TP11 "RCU-0C" TE_RCU 1175,1692 r90 top
TP12 "RCU-0C" TE_RCU 583,1292 r270 top
TP13 "RCU-0C" TE_RCU 1356,903 r0 top
TP14 "RCU-0C" TE_RCU 578,1067 r270 top
TP15 "RCU-0C" TE_RCU 1773,1336 r90 top
TP16 "RCU-0C" TE_RCU 583,1399 r90 top
TP17 "RCU-0C" TE_RCU 1356,1131 r0 top
TP18 "RCU-0C" TE_RCU 1352,670 r0 top
TP19 "RCU-0C" TE_RCU 1198,961 r90 top
TP20 "RCU-0C" TE_RCU 1169,188 r180 top
TP21 "RCU-0C" TE_RCU 1172,370 r180 top
TP22 "RCU-0C" TE_RCU 1170,1369 r90 top
TP23 "RCU-0C" TE_RCU 485,1880 r180 top
TP24 "RCU-0C" TE_RCU 1381,1875 r180 top
TP25 "RCU-0C" TE_RCU 310,363 r180 top
TP26 "RCU-0C" TE_RCU 1801,244 r180 top
TP27 "RCU-0C" TE_RCU 863,657 r180 top
TP28 "RCU-0C" TE_RCU 904.15,1112.11 r180 top
TP29 "RCU-0C" TE_RCU 1500.4,861.91 r90 top
TP30 "RCU-0C" TE_RCU 902.76,1844.5 r180 top
TP31 "RCU-0C" TE_RCU 1502,1064 r90 top
TP32 "RCU-0C" TE_RCU 1774,1453 r90 top
TP33 "RCU-0C" TE_RCU 1497,633 r90 top
TP34 "RCU-0C" TE_RCU 848,1273 r180 top
U1 "TPS22976DPUR" DPU0014A 1459,278.21 r0 top
U2 "TCA9535RTWR" RTW0024B 910,266 r0 top
U3 "TPS62821DLCR" DLC0008A 753.76,728.5 r90 top
U4 "TLV62568PDRL" DRL0006A 693,1021 r90 top
U5 "TLV74228PDQNR" DQN0004A 1368.66,843.61 r180 top
U6 "TLV62568PDRL" DRL0006A 696,1749 r90 top
U7 "TLV74218PDQNR" DQN0004A 1363.33,1067.61 r180 top
U8 "TLV62568PDRL" DRL0006A 1388,1398 r90 top
U9 "TLV74218PDQNR" DQN0004A 1367.66,609.61 r180 top
U10 "TPS62821DLCR" DLC0008A 730,1345 r90 top
U11 "TPS61169DCKR" DCK0005A_N 1389.66,1745.61 r180 top
ZZ1 "This Assembly Note is for PCB labels only" AssemblyNoteLabel 1321,4965 r90 top
ZZ2 "These assemblies are ESD sensitive, ESD precautions shall be observed." AssemblyNote 1284,5094 r90 top
ZZ3 "These assemblies must be clean and free from flux and all contaminants. Use of no clean flux is not acceptable." AssemblyNote 1267,5205 r90 top
ZZ4 "These assemblies must comply with workmanship standards IPC-A-610 Class 2, unless otherwise specified." AssemblyNote 1267,5311 r90 top

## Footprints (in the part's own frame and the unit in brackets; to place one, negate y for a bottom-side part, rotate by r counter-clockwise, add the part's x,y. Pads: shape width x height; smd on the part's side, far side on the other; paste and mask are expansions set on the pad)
0201 [mm] "Data from Kemet datasheet CC101_COM dated 7/28/11"
  rect 0.46x0.42 smd mask+0.048: 1(-0.33,0) 2(0.33,0)
  body extent -0.31,-0.16 0.31,0.16, height 0.26
0201_033 [mm] "SMD, 2-Leads, Height 0.33mm"
  rect 0.46x0.42 smd mask+0.048: 1(-0.33,0) 2(0.33,0)
  body extent -0.31,-0.16 0.31,0.16, height 0.33
0402 [mm] "0402 from SM-752 data"
  rect 0.8x0.6 smd: 1(-0.6,0) 2(0.6,0)
  silkscreen extent -1.22,-0.52 1.22,0.52, body extent -0.55,-0.3 0.55,0.3, height 0.6
0402S [mil] "Based on C0402S footprint from PADS legacy"
  rect 15x24 smd: 1(-20,0) 2(20,0)
  body extent -22,-12 22,12, height 24
0603 [mm] "0603 from SM-752 data"
  rect 1x0.95 smd: 1(-0.8,0) 2(0.8,0)
  silkscreen extent -1.52,-0.69 1.52,0.69, body extent -0.87,-0.47 0.87,0.47, height 1
0603S [mil]
  rect 20x35 smd: 1(-30,0) 2(30,0)
  body extent -34,-19 34,19, height 39
0805_HV [mil] "0805 with 30mil clearance between pads"
  rect 50x63 smd: 1(-40,0) 2(40,0)
  silkscreen extent -74,-40 74,40, body extent -43,-29 43,29, height 57
AssemblyNote [mil] "Assembly Note"
AssemblyNoteLabel [mil] "Assembly Note for PCB Labels"
Bumpon_SJ5003Transparent [mil] "3M Hemispherical Bumpon transparent"
  round 1 on Mech4: 0(0,0)
  silkscreen extent -228,-228 228,228, body extent -219,-219 219,219, height 197
DCK0005A_N [mm] "SOT353, 5-Leads, Body 2x1.3mm, Pitch 0.65mm, Lead Span 2.1mm, IPC Medium Density"
  rrect25% 0.85x0.4 smd: 1(-1.125,0.65) 2(-1.125,0) 3(-1.125,-0.65) 4(1.125,-0.65) 5(1.125,0.65)
  silkscreen extent -1.48,-1.02 0.55,1.1, body extent -1.14,-1 1.14,1, height 0.95
DFE252012P [mm] "TOKO, Pad sizes increased as per request"
  rect 0.9x2 smd: 1(-1.05,0) 2(1.05,0)
  silkscreen extent -0.3,-1.2 0.3,1.2, body extent -1.35,-1.1 1.35,1.1, height 1.2
DLC0008A [mm] "VSON-HR-8"
  rrect40% 0.55x0.25 smd: 1(-0.675,0.75) 2(-0.675,0.25) 3(-0.675,-0.25) 4(-0.675,-0.75) 5(0.675,-0.75) 6(0.675,-0.25) 7(0.675,0.25) 8(0.675,0.75)
  silkscreen extent -0.75,-1.15 0.75,1.15, body extent -0.8,-1.05 0.8,1.05, height 1.02
DPU0014A [mm] "SON-14"
  rrect67% 0.65x0.3 smd paste-0.05 mask-0.05: 1(-0.925,1.2) 2(-0.925,0.8) 6(-0.925,-0.8) 7(-0.925,-1.2) 8(0.925,-1.2) 9(0.925,-0.8) 13(0.925,0.8) 14(0.925,1.2)
  rrect50% 0.55x0.2 smd: 3(-0.925,0.4) 4(-0.925,0) 5(-0.925,-0.4) 10(0.925,-0.4) 11(0.925,0) 12(0.925,0.4)
  rrect12% 0.85x1.11 on Top Paste: 15(0,-0.655) 15(0,0.655)
  rrect11% 0.9x2.5 smd paste-0.5: 15(0,0)
  Top Layer region: 0.6,0.75 0.6,1.25 0.613,1.3 0.65,1.337 0.7,1.35 0.7,1.35 1.15,1.35 1.188,1.342 1.221,1.321 1.242,1.288 1.25,1.25 1.25,1.25 1.25,0.75 1.242,0.712 1.221,0.679 1.188,0.658 1.15,0.65 1.15,0.65 0.7,0.65 0.662,0.658 0.629,0.679 0.608,0.712 0.6,0.75
  Top Layer region: 0.6,-0.75 0.6,-1.25 0.613,-1.3 0.65,-1.337 0.7,-1.35 0.7,-1.35 1.15,-1.35 1.188,-1.342 1.221,-1.321 1.242,-1.288 1.25,-1.25 1.25,-1.25 1.25,-0.75 1.242,-0.712 1.221,-0.679 1.188,-0.658 1.15,-0.65 1.15,-0.65 0.7,-0.65 0.662,-0.658 0.629,-0.679 0.608,-0.712 0.6,-0.75
  Top Layer region: -0.6,-0.75 -0.6,-1.25 -0.613,-1.3 -0.65,-1.337 -0.7,-1.35 -0.7,-1.35 -1.15,-1.35 -1.188,-1.342 -1.221,-1.321 -1.242,-1.288 -1.25,-1.25 -1.25,-1.25 -1.25,-0.75 -1.242,-0.712 -1.221,-0.679 -1.188,-0.658 -1.15,-0.65 -1.15,-0.65 -0.7,-0.65 -0.662,-0.658 -0.629,-0.679 -0.608,-0.712 -0.6,-0.75
  Top Layer region: -0.6,0.75 -0.6,1.25 -0.613,1.3 -0.65,1.337 -0.7,1.35 -0.7,1.35 -1.15,1.35 -1.188,1.342 -1.221,1.321 -1.242,1.288 -1.25,1.25 -1.25,1.25 -1.25,0.75 -1.242,0.712 -1.221,0.679 -1.188,0.658 -1.15,0.65 -1.15,0.65 -0.7,0.65 -0.662,0.658 -0.629,0.679 -0.608,0.712 -0.6,0.75
  silkscreen extent -1.15,-1.65 1.15,1.65, body extent -1.05,-1.55 1.05,1.55, height 0.8
DQN0004A [mm] "SON, 0.65mm pitch"
  rect 0.25x0.31 smd paste-1 mask-0.31: 1(-0.535,0.325) 2(-0.535,-0.325) 3(0.535,-0.325) 4(0.535,0.325)
  rect 0.58x0.58 smd rot 45 paste-0.065 mask-0.05: 5(0,0)
  Top Layer region: -0.66,-0.48 -0.2,-0.48 -0.2,-0.379 -0.409,-0.17 -0.66,-0.17
  Top Layer region: 0.66,-0.48 0.2,-0.48 0.2,-0.379 0.409,-0.17 0.66,-0.17
  Top Layer region: 0.66,0.48 0.2,0.48 0.2,0.379 0.409,0.17 0.66,0.17
  Top Layer region: -0.66,0.48 -0.2,0.48 -0.2,0.379 -0.409,0.17 -0.66,0.17
  silkscreen extent -0.88,-0.7 0.88,0.7, body extent -0.53,-0.53 0.53,0.53, height 0.42
DRL0006A [mm] "SOTFL, 6-Flat Leads, Body 1.2x1.6x0.6mm, Pitch 0.5mm, TI recommended"
  rrect33% 0.67x0.3 smd: 1(-0.74,0.5) 2(-0.74,0) 3(-0.74,-0.5) 4(0.74,-0.5) 5(0.74,0) 6(0.74,0.5)
  silkscreen extent -0.9,-0.95 0.5,0.95, body extent -0.8,-0.8 0.8,0.8, height 0.61
FCC_disclaimer [mil]
Fiducial10-20 [mm]
  round 1 smd mask+0.5: 1(0,0)
  Top Layer keep-out circle w1.178: c0,0 r0.5
Label_650x200 [mil] "Thermal Transfer Label"
  round 1 on Mech14: 0(0,0)
  silkscreen extent -325,-100 325,100, body extent -325,-100 325,100, height 1
Pb-Free_Overlay_Small [mil]
  silkscreen extent -46,-46 46,46
RTW0024B [mm] "QFN, 24-Leads, Body 4x4mm, Pitch 0.5mm, Thermal Pad 2.45x2.45mm, TI Recommended"
  rrect42% 0.6x0.24 smd: 1(-1.9,1.25) 2(-1.9,0.75) 3(-1.9,0.25) 4(-1.9,-0.25) 5(-1.9,-0.75) 6(-1.9,-1.25) 13(1.9,-1.25) 14(1.9,-0.75) 15(1.9,-0.25) 16(1.9,0.25) 17(1.9,0.75) 18(1.9,1.25)
  rrect42% 0.24x0.6 smd: 7(-1.25,-1.9) 8(-0.75,-1.9) 9(-0.25,-1.9) 10(0.25,-1.9) 11(0.75,-1.9) 12(1.25,-1.9) 19(1.25,1.9) 20(0.75,1.9) 21(0.25,1.9) 22(-0.25,1.9) 23(-0.75,1.9) 24(-1.25,1.9)
  rrect4% 2.45x2.45 smd paste-1.225: 25(0,0)
  silkscreen extent -2.22,-2.22 2.22,2.22, body extent -2.07,-2.07 2.07,2.07, height 0.81
Samtec_HTSW-105-07-G-S [mm] "Samtec 100mil, 1x5, 230 mil above insulator"
  rrect6% 1.65x1.65 hole 1.016: 1(-5.08,0)
  round 1.65 hole 1.016: 2(-2.54,0) 3(0,0) 4(2.54,0) 5(5.08,0)
  silkscreen extent -7.11,-1.27 6.35,1.27, body extent -6.35,-1.27 6.35,1.27, height 8.38
Samtec_RSM-110-02-x-D [mm] "Receptacle, 1.27mm, 10x2, SMT"
  rrect14% 0.74x1.84 smd: 1(-5.715,2.825) 2(-5.715,-2.825) 3(-4.445,2.825) 4(-4.445,-2.825) 5(-3.175,2.825) 6(-3.175,-2.825) 7(-1.905,2.825) 8(-1.905,-2.825) 9(-0.635,2.825) 10(-0.635,-2.825) 11(0.635,2.825) 12(0.635,-2.825) 13(1.905,2.825) 14(1.905,-2.825) 15(3.175,2.825) 16(3.175,-2.825) 17(4.445,2.825) 18(4.445,-2.825) 19(5.715,2.825) 20(5.715,-2.825)
  body extent -6.48,-3.24 6.48,3.24, height 6.1
SOD-523 [mm] "NXP Semiconductor recommended land pattern, nominal STEP model"
  rect 0.8x0.6 smd paste-0.05: 1(-0.55,0) 2(0.55,0)
  silkscreen extent -1.65,-0.66 1.2,0.66, body extent -0.8,-0.4 0.8,0.4, height 0.72
TE_RCU [mm] "SMD, 1-Leads, Body 1.6x0.8mm"
  rrect8% 2.4x1.2 smd: 1(0,0)
  body extent -0.8,-0.45 0.8,0.45, height 1.15
WAGO_2059-302 [mm] "Terminal Block, 3mm, 2-Pole, Body 7.4x5.9mm"
  rect 1.4x2.5 smd: 1(-1.5,3.1) 1(-1.5,-3.1) 2(1.5,3.1) 2(1.5,-3.1)
  silkscreen extent -3.4,-3.45 2.95,4.05, body extent -2.95,-3.9 2.95,3.95, height 2.7
WE-PMCI_0805 [mm] "SMD, 2-Leads, Body 2x1.25mm"
  rect 0.7x1.45 smd: 1(-0.75,0) 2(0.75,0)
  silkscreen extent -0.1,-0.72 0.1,0.72, body extent -1,-0.62 1,0.63, height 1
